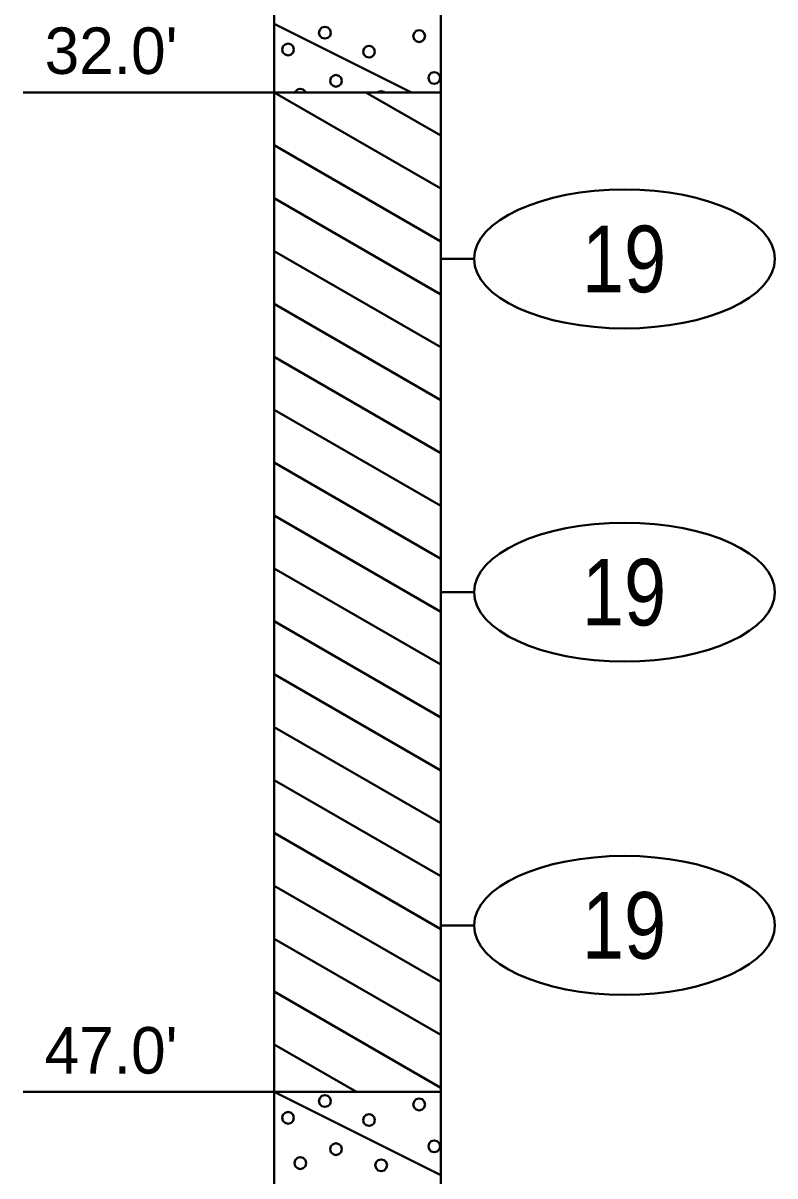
# Model space of a CAD drawing. Extents: x -76 to 974, y -1080 to -735.
# Drawn here: x -70.92 to -59.64, y -814.97 to -797.67 of the extents above; entities that cross this region are included whole.
import ezdxf
from ezdxf.enums import TextEntityAlignment as Align

# ---------------------------------------------------------------- set-up
doc = ezdxf.new("R2010")
doc.units = 0
doc.header["$LTSCALE"] = 0.36
doc.layers.add('27', color=7, linetype='Continuous', lineweight=40)

msp = doc.modelspace()

# ---------------------------------------------------------------- linework, layer by layer
at = {"layer": '27'}
for p, q in [((-67.154, -783.7053), (-67.154, -798.7053)), ((-64.654, -798.7053), (-64.654, -783.7053)), ((-67.154, -797.6753), (-65.094, -798.7053)), ((-70.9214, -798.7053), (-67.154, -798.7053)), ((-67.154, -798.7053), (-64.654, -798.7053)), ((-67.154, -798.7053), (-64.654, -800.1487)), ((-67.154, -798.7053), (-67.154, -813.7053)), ((-65.7792, -798.7053), (-64.654, -799.3549)), ((-65.7792, -798.7053), (-64.654, -799.3549)), ((-64.654, -813.7053), (-64.654, -798.7053)), ((-67.154, -799.499), (-64.654, -800.9424)), ((-67.154, -799.499), (-64.654, -800.9424)), ((-67.154, -800.2928), (-64.654, -801.7362)), ((-67.154, -801.0865), (-64.654, -802.5299)), ((-67.154, -801.0865), (-64.654, -802.5299)), ((-64.154, -801.2053), (-64.654, -801.2053)), ((-67.154, -801.8803), (-64.654, -803.3237)), ((-67.154, -802.674), (-64.654, -804.1174)), ((-67.154, -802.674), (-64.654, -804.1174)), ((-67.154, -803.4678), (-64.654, -804.9112)), ((-67.154, -804.2615), (-64.654, -805.7049)), ((-67.154, -804.2615), (-64.654, -805.7049)), ((-67.154, -805.0553), (-64.654, -806.4987)), ((-67.154, -805.849), (-64.654, -807.2924)), ((-67.154, -805.849), (-64.654, -807.2924)), ((-64.154, -806.2053), (-64.654, -806.2053)), ((-67.154, -806.6428), (-64.654, -808.0862)), ((-67.154, -807.4365), (-64.654, -808.8799)), ((-67.154, -807.4365), (-64.654, -808.8799)), ((-67.154, -808.2303), (-64.654, -809.6737)), ((-67.154, -809.024), (-64.654, -810.4674)), ((-67.154, -809.024), (-64.654, -810.4674)), ((-67.154, -809.8178), (-64.654, -811.2612)), ((-67.154, -810.6115), (-64.654, -812.0549)), ((-67.154, -810.6115), (-64.654, -812.0549)), ((-64.154, -811.2053), (-64.654, -811.2053)), ((-67.154, -811.4053), (-64.654, -812.8487)), ((-67.154, -812.199), (-64.654, -813.6424)), ((-67.154, -812.199), (-64.654, -813.6424)), ((-67.154, -812.9928), (-65.9199, -813.7053)), ((-70.9214, -813.7053), (-67.154, -813.7053)), ((-67.154, -813.7053), (-64.654, -813.7053)), ((-67.154, -813.7053), (-64.654, -814.9553)), ((-67.154, -813.7053), (-67.154, -817.7053)), ((-64.654, -817.7053), (-64.654, -813.7053))]:
    msp.add_line(p, q, dxfattribs=at)
for points in [[(-66.3034, -797.8104), (-66.3153, -797.766), (-66.3478, -797.7334), (-66.3923, -797.7215), (-66.4367, -797.7334), (-66.4693, -797.766), (-66.4812, -797.8104), (-66.4693, -797.8549), (-66.4367, -797.8874), (-66.3923, -797.8993), (-66.3478, -797.8874), (-66.3153, -797.8549)], [(-64.8885, -797.8613), (-64.9004, -797.8168), (-64.9329, -797.7843), (-64.9774, -797.7724), (-65.0218, -797.7843), (-65.0543, -797.8168), (-65.0663, -797.8613), (-65.0543, -797.9057), (-65.0218, -797.9383), (-64.9774, -797.9502), (-64.9329, -797.9383), (-64.9004, -797.9057)], [(-66.8564, -798.0621), (-66.8683, -798.0177), (-66.9008, -797.9851), (-66.9453, -797.9732), (-66.9897, -797.9851), (-67.0223, -798.0177), (-67.0342, -798.0621), (-67.0223, -798.1066), (-66.9897, -798.1391), (-66.9453, -798.151), (-66.9008, -798.1391), (-66.8683, -798.1066)], [(-65.641, -798.0952), (-65.653, -798.0507), (-65.6855, -798.0182), (-65.7299, -798.0063), (-65.7744, -798.0182), (-65.8069, -798.0507), (-65.8188, -798.0952), (-65.8069, -798.1396), (-65.7744, -798.1722), (-65.7299, -798.1841), (-65.6855, -798.1722), (-65.653, -798.1396)], [(-66.1368, -798.5325), (-66.1487, -798.488), (-66.1813, -798.4555), (-66.2257, -798.4436), (-66.2702, -798.4555), (-66.3027, -798.488), (-66.3146, -798.5325), (-66.3027, -798.5769), (-66.2702, -798.6095), (-66.2257, -798.6214), (-66.1813, -798.6095), (-66.1487, -798.5769)], [(-64.6622, -798.4893), (-64.6741, -798.4448), (-64.7066, -798.4123), (-64.7511, -798.4004), (-64.7955, -798.4123), (-64.8281, -798.4448), (-64.84, -798.4893), (-64.8281, -798.5337), (-64.7955, -798.5663), (-64.7511, -798.5782), (-64.7066, -798.5663), (-64.6741, -798.5337)], [(-66.684, -798.6965), (-66.7165, -798.664), (-66.7609, -798.6521), (-66.8054, -798.664), (-66.8379, -798.6965), (-66.8403, -798.7053), (-66.6816, -798.7053)], [(-65.5037, -798.697), (-65.5482, -798.6851), (-65.5926, -798.697), (-65.6008, -798.7053), (-65.4955, -798.7053)], [(-66.3033, -813.8416), (-66.3152, -813.7972), (-66.3477, -813.7646), (-66.3922, -813.7527), (-66.4366, -813.7646), (-66.4692, -813.7972), (-66.4811, -813.8416), (-66.4692, -813.8861), (-66.4366, -813.9186), (-66.3922, -813.9305), (-66.3477, -813.9186), (-66.3152, -813.8861)], [(-64.8885, -813.8925), (-64.9004, -813.8481), (-64.9329, -813.8155), (-64.9774, -813.8036), (-65.0218, -813.8155), (-65.0543, -813.8481), (-65.0663, -813.8925), (-65.0543, -813.937), (-65.0218, -813.9695), (-64.9774, -813.9814), (-64.9329, -813.9695), (-64.9004, -813.937)], [(-66.8564, -814.0934), (-66.8683, -814.0489), (-66.9008, -814.0164), (-66.9453, -814.0045), (-66.9897, -814.0164), (-67.0223, -814.0489), (-67.0342, -814.0934), (-67.0223, -814.1378), (-66.9897, -814.1704), (-66.9453, -814.1823), (-66.9008, -814.1704), (-66.8683, -814.1378)], [(-65.641, -814.1264), (-65.653, -814.082), (-65.6855, -814.0495), (-65.7299, -814.0375), (-65.7744, -814.0495), (-65.8069, -814.082), (-65.8188, -814.1264), (-65.8069, -814.1709), (-65.7744, -814.2034), (-65.7299, -814.2153), (-65.6855, -814.2034), (-65.653, -814.1709)], [(-66.1368, -814.5638), (-66.1487, -814.5193), (-66.1813, -814.4868), (-66.2257, -814.4749), (-66.2702, -814.4868), (-66.3027, -814.5193), (-66.3146, -814.5638), (-66.3027, -814.6082), (-66.2702, -814.6408), (-66.2257, -814.6527), (-66.1813, -814.6408), (-66.1487, -814.6082)], [(-64.6622, -814.5205), (-64.6741, -814.4761), (-64.7066, -814.4436), (-64.7511, -814.4316), (-64.7955, -814.4436), (-64.8281, -814.4761), (-64.84, -814.5205), (-64.8281, -814.565), (-64.7955, -814.5975), (-64.7511, -814.6094), (-64.7066, -814.5975), (-64.6741, -814.565)], [(-66.672, -814.7723), (-66.684, -814.7278), (-66.7165, -814.6953), (-66.7609, -814.6834), (-66.8054, -814.6953), (-66.8379, -814.7278), (-66.8498, -814.7723), (-66.8379, -814.8167), (-66.8054, -814.8492), (-66.7609, -814.8612), (-66.7165, -814.8492), (-66.684, -814.8167)], [(-65.4593, -814.8053), (-65.4712, -814.7609), (-65.5037, -814.7283), (-65.5482, -814.7164), (-65.5926, -814.7283), (-65.6251, -814.7609), (-65.6371, -814.8053), (-65.6251, -814.8498), (-65.5926, -814.8823), (-65.5482, -814.8942), (-65.5037, -814.8823), (-65.4712, -814.8498)]]:
    msp.add_lwpolyline(points, close=True, dxfattribs=at)
for centre in [(-61.8966, -801.2053), (-61.8966, -806.2053), (-61.8966, -811.2053)]:
    msp.add_ellipse(centre, major_axis=(2.2574, 0), ratio=0.461538, dxfattribs=at)

# ---------------------------------------------------------------- texts
for s, p in [("32.0'", (-70.5974, -798.4289)), ("47.0'", (-70.5974, -813.4289))]:
    msp.add_text(s, height=0.6976, dxfattribs=at).set_placement(p)
at = {"layer": '27', "width": 0.85}
for p in [(-61.904, -801.7052), (-61.904, -806.7052), (-61.904, -811.7052)]:
    msp.add_text('19', height=1, dxfattribs=at).set_placement(p, align=Align.CENTER)

doc.saveas('drawing.dxf')
